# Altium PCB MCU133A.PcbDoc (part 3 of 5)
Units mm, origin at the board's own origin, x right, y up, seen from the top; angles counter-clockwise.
Board outline 58.42 x 139.7 mm, 4 copper layers (Top Signal, GND, PWR, Bottom Signal), stack 1.565 mm thick; 278 components, 226 nets, 1057 pads, 868 vias.
Unrouted connection lines stored in the file: 237.
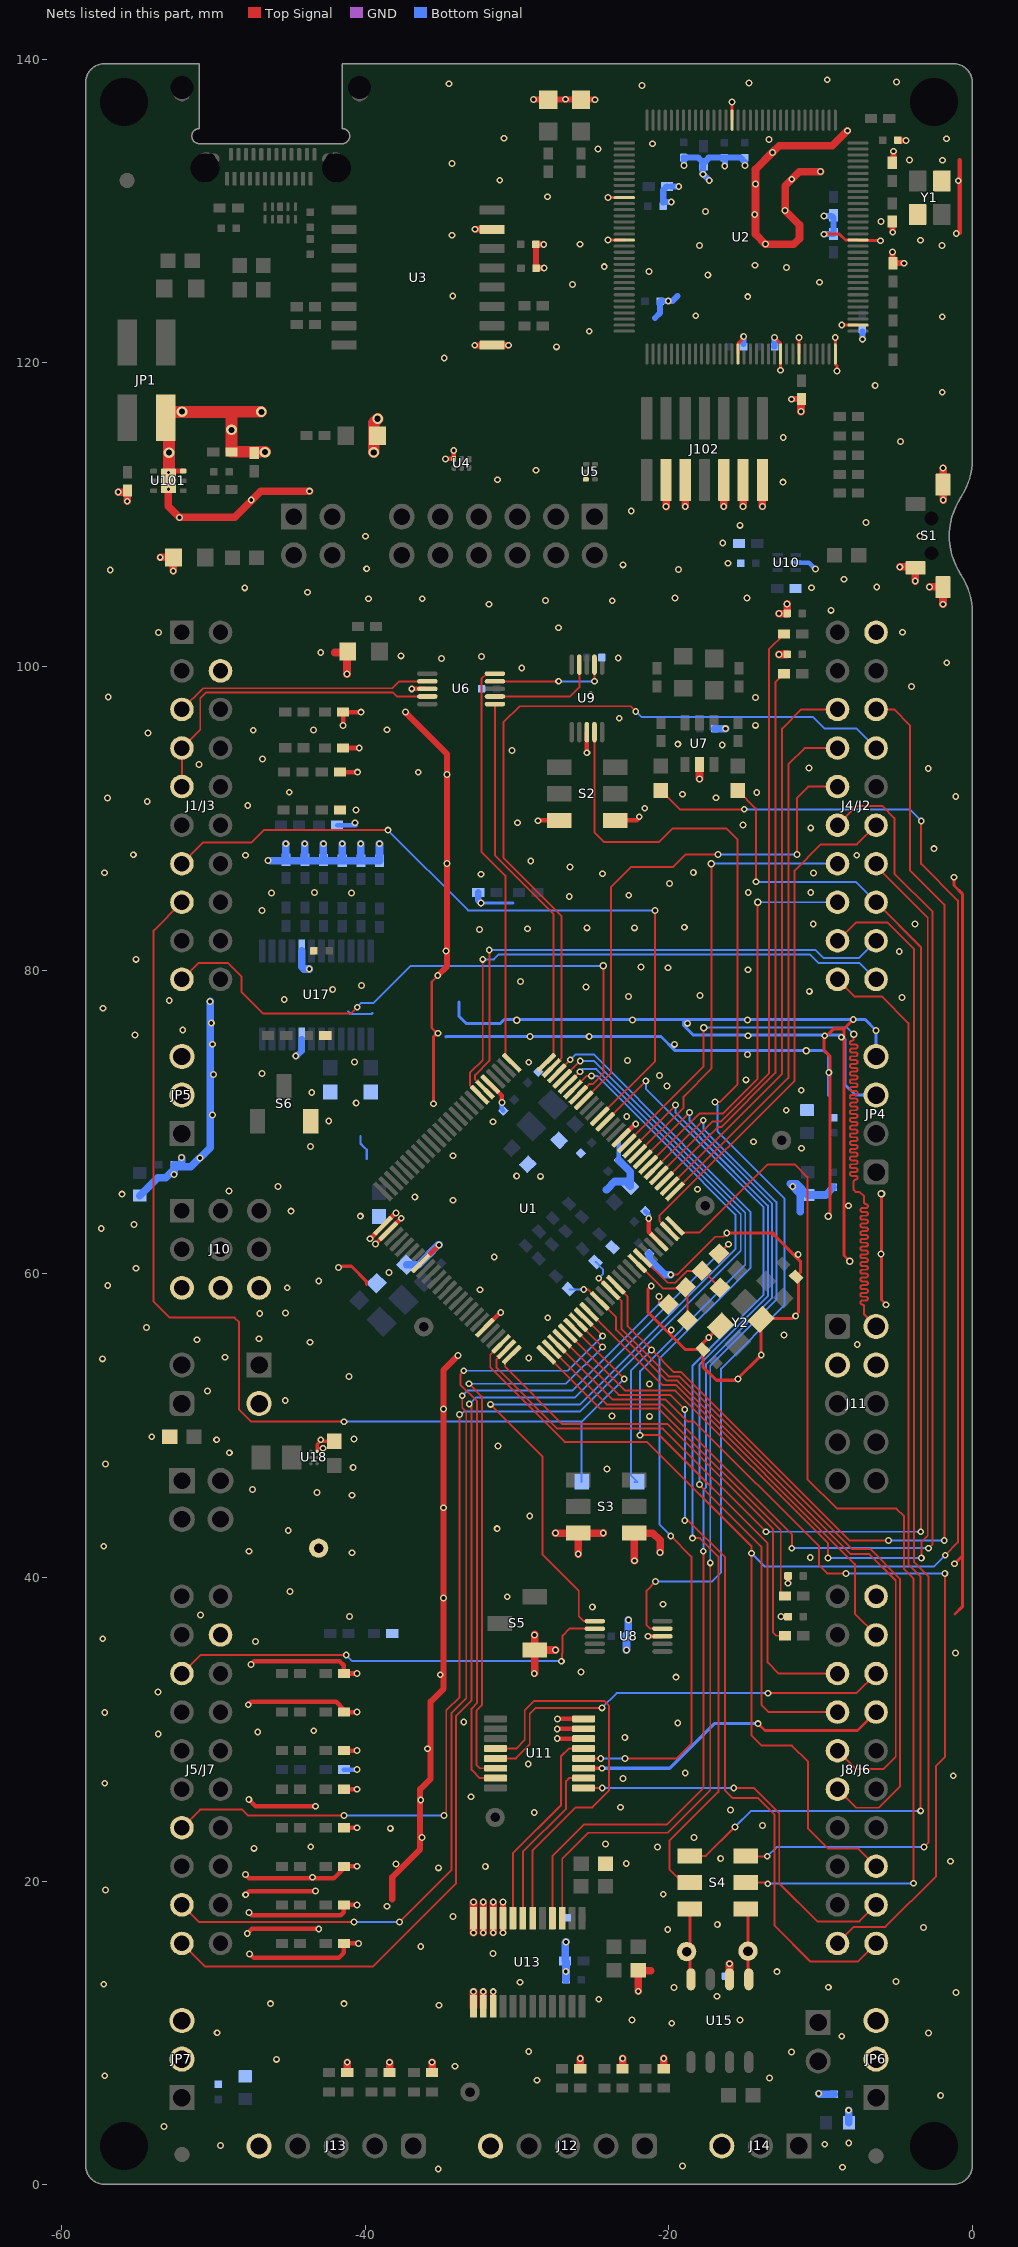
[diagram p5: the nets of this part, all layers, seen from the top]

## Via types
v1: diameter 0.45, hole 0.25, Top Signal to Bottom Signal, tented both sides, 822 vias
v2: diameter 0.5, hole 0.3, Top Signal to Bottom Signal, tented both sides, 22 vias
v3: diameter 0.7, hole 0.4, Top Signal to Bottom Signal, tented both sides, 17 vias
v4: diameter 0.4, hole 0.2, Top Signal to Bottom Signal, tented both sides, 5 vias
v5: diameter 0.5, hole 0.2, Top Signal to Bottom Signal, tented both sides, 2 vias

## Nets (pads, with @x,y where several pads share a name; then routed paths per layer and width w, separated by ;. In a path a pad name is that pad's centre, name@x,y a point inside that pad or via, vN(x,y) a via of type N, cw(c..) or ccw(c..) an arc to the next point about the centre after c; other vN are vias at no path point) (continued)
GND: C1.1 C2.1 C6.2 C7.2 C9.1 C10.1 C11.1 C12.1 C14.1 C15.2 C16.2 C17.2 C18.1 C19.1 C20.1 C21.1 C22.1 C24.2 C25.2 C26.2 C27.2 C28.2 C29.2 C30.2 C31.2 C32.2 C33.2 C34.2 C35.2 C36.2 C37.2 C38.2 C39.2 C40.2 C41.2 C42.2 C43.2 C44.1 C45.2 C46.1 C50.1 C51.1 C52.1 C53.1 C54.1 C55.1 C56.2 C57.2 C58.1 C59.2 C60.1 C61.2 C62.2 C63.2 C64.2 C65.1 C66.1 C67.2 C68.2 C69.2 C70.2 C71.2 C72.2 C73.2 C74.2 C75.2 C76.2 C77.2 C78.2 C81.1 C82.1 C83.1 C84.1 C100.2 C103.2 C107.2 C108.2 C109.2 C110.2 C111.1 C112.1 C113.1 C114.2 C115.1 C116.2 C117.1 C118.2 C119.1 C120.2 C121.2 C122.2 J1/J3.22 J4/J2.20 J5/J7.62 J8/J6.60 J10.7 J10.8 J10.9 J11.3 J11.4 J12.5 J13.5 J14.3 J15.2 J102.3 J102.5 J102.9 J102.11 J102.13 JP1.4 JP4.3 JP4.4 JP5.2 JP5.3 JP6.2 JP6.3 JP7.2 JP7.3 LED0.1 LED1.1 LED2.2 LED3.2 LED6.1 R52.1 R53.2 R67.1 R68.1 R83.2 R102.1 R107.2 R108.2 S1.1 S1.2 S1.3 S2.3 S2.6 S3.1 S3.4 S5.1 S6.3 TP6.1 U1.5 U1.26 U1.27 U1.33 U1.45 U1.72 U1.86 U2.10 U2.17 U2.48 U2.55 U2.58 U2.64 U2.66 U2.80 U2.114 U3.9 U3.15 U4.3 U5.3 U6.3 U7.2 U8.3 U9.3 U10.5 U11.6 U11.7 U11.8 U13.9 U13.10 U13.11 U13.12 U13.13 U13.14 U13.15 U15.2 U17.5 U17.20 U18.A2 U101.3 U101.7@-52.96,112.224 Y1.2 Y1.4 Y2.2 Y2.4 | length 575.8
  Top Signal w0.127: v1(-19.871,59.94) -19.436,59.94 -16.937,62.438 -16.43,62.438 v1(-16.189,62.68)
  Top Signal w0.15: v1@-35.273,75.837 -35.621,76.184 -35.621,79.234 v1(-35.218,79.637)
  Top Signal w0.2: -41.506,60.494 -40.909,60.494 -39.921,59.506 -39.921,59.302 ; v1(-35.496,71.197) -35.496,75.614 v1@-35.273,75.837 ; v1(-24.012,128.084) U2.17@-22.936,128.084 ; v1(-24.012,130.884) U2.10@-22.936,130.884 ; v1(-21.159,59.19) -21.388,58.961 -21.388,57.479 -18.929,55.02 C41.2@-17.757,55.02 ; Y2.4@-16.605,56.566 -17.757,55.414 C41.2@-17.757,55.02 ; v1(-16.189,62.68) -13.188,62.68 ; U2.114@-15.836,135.984 v1(-15.836,137.174) ; U2.48@-15.436,120.584 -15.436,121.294 -15.072,121.658 v1(-15.072,121.739) ; -13.075,62.567 -11.34,60.832 -11.34,60.076 C42.2@-11.616,59.8 -11.456,59.64 -11.456,57.456 -11.86,57.053 -13.855,57.053 Y2.2@-13.918,56.991 v1(-13.918,54.64) -15.571,52.986 -16.867,52.986 -17.757,53.876 C41.2@-17.757,55.02 ; v1(-13.034,121.675) -13.032,121.675 -12.636,121.279 v1(-12.636,119.508) ; U2.58@-11.436,120.584 v1(-11.436,121.66) ; v1(-9.78,128.474) -8.752,128.474 -8.362,128.084 U2.80@-7.536,128.084 -7.506,128.054 -6.07,128.054 v1(-6.061,128.046) ; v2@-9.399,63.888 -9.399,74.334 -9.78,74.715 -9.78,75.503 -9.145,76.138 -8.459,76.138 ; v1(-9.036,121.66) U2.64@-9.036,120.584 -9.036,119.91 -8.917,119.791 v1(-8.917,119.453) ; v1(-8.612,122.484) U2.66@-7.536,122.484 ; v2(-8.078,60.825) -8.459,61.206 -8.459,76.138 ; v1(-7.85,76.747) -8.459,76.138 ; v2(-5.995,65.259) -5.995,58.266 v1(-5.691,57.961) ; v1(-1.22,86.12) -1.22,85.568 -0.646,84.994 -0.646,41.442 ; v1(-1.183,40.904) -0.646,41.442 ; -1.153,37.584 -0.646,38.092 -0.646,41.442 ; -0.646,42.747 -0.646,41.442
  Top Signal w0.23: U18.A2@-43.171,48.298 -43.171,48.772 -42.978,48.965 C110.2@-42.037,48.965
  Top Signal w0.3: U101.7@-52.96,112.224 -52.96,112.491 -52.921,112.53 -52.577,112.874 U101.3@-51.985,112.874 ; v1(-47.883,20.422) -47.653,20.192 -42.058,20.192 -41.403,20.847 C75.2@-41.403,20.969 v1(-40.539,20.969) ; v1(-47.873,19.097) -47.631,19.339 v1(-43.281,19.339) ; v1(-47.771,16.552) -47.479,16.844 v1(-43.063,16.844) ; v1(-47.698,31.614) -47.511,31.802 -41.908,31.802 -41.403,31.296 C37.2@-41.403,31.129 v1(-40.539,31.129) ; v1(-47.664,25.374) -47.222,24.932 v1(-43.271,24.932) ; v1(-47.658,17.937) -47.466,17.744 -41.606,17.744 -41.403,17.947 C38.2@-41.403,18.429 v1(-40.539,18.429) ; v1(-47.616,15.202) -47.353,14.939 -41.728,14.939 -41.403,15.265 C25.2@-41.403,15.889 -40.44,15.889 v1(-40.438,15.887) ; v1(-47.523,34.272) -47.306,34.489 -41.688,34.489 -41.403,34.204 C107.2@-41.403,33.669 v1(-40.539,33.669) ; C31.2@-41.661,93.039 v1(-40.514,93.039) ; C39.2@-41.456,94.629 -40.398,94.629 v1(-40.39,94.637) ; v1@-41.454,96.111 C28.2@-41.454,96.999 -40.293,96.999 v1(-40.285,96.991) ; C40.2@-41.403,23.509 v1(-40.539,23.509) ; C27.2@-41.403,26.049 v1(-40.539,26.049) ; C35.2@-41.403,28.589 v1(-40.539,28.589) ; v1(-39.677,62.309) U1.26@-38.828,63.159 v1(-37.979,64.008) ; v1(-39.324,61.956) U1.27@-38.475,62.805 v1(-37.625,63.654) ; v1(-36.933,98.527) U6.3@-36.072,98.527 ; U1.33@-36.353,60.684 -35.133,61.903 v1(-35.129,61.903) ; v1(-34.704,113.668) -34.165,113.668 U4.3@-34.154,113.679 ; U4.3@-34.165,113.69 v1(-34.165,114.229) ; U1.45@-32.111,56.441 v1@-31.105,57.447 ; U1.5@-31.757,72.492 -31.006,71.741 -31.006,71.285 v1(-30.994,71.273) ; v1@-28.67,89.865 S2.3@-27.224,89.865 ; v1(-27.353,30.022) -27.346,30.029 U11.7@-25.613,30.029 ; v1(-27.348,29.392) -27.336,29.379 U11.6@-25.613,29.379 ; v1(-27.326,30.673) -27.32,30.679 U11.8@-25.613,30.679 ; v1(-25.401,94.315) -25.398,94.317 U9.3@-25.398,95.674 ; S2.6@-23.524,89.865 -22.116,89.865 v1@-21.911,90.07 ; U1.86@-23.13,68.957 -22.223,69.864 v1(-22.175,69.864) v1@-22.175,69.882 ; v1(-21.363,36.121) U8.3@-20.42,36.121 ; v1(-21.321,63.644) -21.321,62.763 U1.72@-20.655,62.098 ; -13.188,62.68 -13.075,62.567 ; v1(-12.611,37.419) C81.1@-12.149,37.419 ; C82.1@-12.148,40.094 -12.148,39.614 v1(-12.146,39.612) ; -0.839,128.561 -0.839,133.339
  Top Signal w0.4: -38.218,18.802 -38.218,20.262 -36.383,22.097 -36.383,26.052 -35.696,26.739 -35.696,31.809 -34.836,32.669 -34.836,53.669 v1(-33.893,54.612) ; v1(-37.351,97.004) -37.351,96.974 -34.606,94.229 -34.606,80.267 v1@-35.227,79.645 ; v1(-32.781,121.154) U3.9@-32.277,121.154 ; v1(-32.761,128.798) U3.15@-31.609,128.798 ; U13.15@-31.569,11.701 v1(-31.569,12.714) ; U3.9@-31.057,121.158 v1(-30.553,121.158) ; v1(-30.919,16.589) U13.9@-30.919,17.602 ; U13.9@-30.919,17.601 v1(-30.919,18.614) ; v1(-28.909,137.336) LED3.2@-28.405,137.336 ; C1.1@-28.755,127.66 -28.755,126.255 C2.1@-28.736,126.236 ; C1.1@-28.755,127.787 v1(-28.238,127.787) ; C2.1@-28.716,126.254 v1(-28.212,126.254) ; LED3.2@-27.692,137.358 LED2.2@-26.301,137.358 ; LED2.2@-25.36,137.331 v1(-24.856,137.331) ; v1(-11.925,117.604) R68.1@-11.421,117.604 ; R67.1@-5.267,126.794 v1(-5.267,127.298) ; v1(-5.257,128.604) C62.2@-5.257,129.108 ; C63.2@-5.207,133.429 v1(-5.207,133.933) ; R67.1@-5.013,126.563 v1(-4.509,126.563) ; C50.1@-4.889,134.64 v1(-4.385,134.64)
  Top Signal w0.5: v1(-56.271,111.484) -55.675,111.484 v1(-55.675,110.888) ; v1(-53.504,107.188) LED6.1@-52.643,107.188 ; U101.7@-52.96,112.224 -52.96,110.544 v1(-52.233,109.817) -48.605,109.817 -46.874,111.548 -46.873,111.547 v1(-43.669,111.547) ; v1(-52.643,106.293) LED6.1@-52.643,107.154 ; -42.007,100.922 LED1.1@-41.214,100.922 ; v1@-41.198,99.499 -41.198,100.906 LED1.1@-41.214,100.922 ; C73.2@-41.184,7.38 v1(-41.184,8.059) ; LED1.1@-41.157,100.979 LED1.1@-41.214,100.922 ; C72.2@-38.39,7.38 v1(-38.39,8.059) ; C71.2@-35.596,7.38 v1(-35.596,8.059) ; U13.13@-32.869,11.701 v1(-32.869,12.714) ; v1(-32.869,16.589) U13.12@-32.869,17.602 ; U13.12@-32.869,17.601 v1(-32.869,18.614) ; U13.14@-32.219,11.701 v1(-32.219,12.714) ; U13.11@-32.219,17.601 v1(-32.219,18.614) ; U13.11@-32.219,17.602 v1(-32.219,16.589) ; v1(-31.569,16.589) U13.10@-31.569,17.602 ; U13.10@-31.569,17.601 v1(-31.569,18.614) ; v1@-28.84,33.687 S5.1@-28.84,35.222 ; v1@-28.84,36.244 S5.1@-28.84,35.222 ; v1(-27.464,35.218) -28.836,35.218 S5.1@-28.84,35.222 ; v1(-27.464,42.916) S3.4@-25.974,42.916 ; v1(-25.97,41.538) -25.974,41.542 S3.4@-25.974,42.916 ; C70.2@-25.836,7.634 v1(-25.836,8.313) ; v1(-24.325,42.927) -24.336,42.916 S3.4@-25.974,42.916 ; C69.2@-23.042,7.634 v1(-23.042,8.313) ; v1(-22.264,41.092) -22.274,41.102 S3.1@-22.274,42.916 -21.051,42.916 -20.575,42.44 v1(-20.575,41.645) ; v1(-22.017,12.739) R53.2@-22.017,14.111 -21.987,14.141 -21.927,14.081 -21.191,14.081 ; S3.1@-22.015,42.902 -21.062,42.902 ; C68.2@-20.331,7.634 v1(-20.331,8.313) ; J102.3@-20.189,112.279 -20.183,112.273 v1(-20.183,110.535) ; v1(-18.919,110.541) J102.5@-18.919,112.279 ; v1(-17.983,92.594) U7.2@-17.983,93.547 ; v1(-16.379,110.541) J102.9@-16.379,112.279 ; U15.2@-16.006,13.526 v1(-16.006,14.557) ; v1(-15.109,110.541) J102.11@-15.109,112.279 ; v1(-13.839,110.541) J102.13@-13.839,112.279 ; v1(-12.752,100.786) C83.1@-12.21,100.786 ; v1(-12.752,103.48) C84.1@-12.21,103.48 ; C84.1@-12.21,103.492 v1(-12.21,104.117) ; v1(-11.294,116.786) R68.1@-11.294,117.647 ; v1(-10.011,132.594) -11.395,132.594 v1(-11.901,132.088) -12.341,131.648 v1(-12.341,130.032) -11.395,129.086 -11.395,128.18 -11.776,127.799 -13.616,127.799 v1(-13.641,127.824) -14.291,128.474 v1(-14.291,131.774) -14.291,132.74 v1(-13.177,133.854) -12.737,134.294 -9.226,134.294 v1(-8.236,135.284) ; v1(-4.785,106.56) S1.3@-3.924,106.56 ; v1(-3.766,105.621) S1.3@-3.766,106.482 ; v1(-2.827,105.241) S1.1@-1.966,105.241 ; v1(-1.944,104.098) S1.1@-1.944,104.959 ; S1.2@-1.936,112.207 v1(-1.936,113.068) ; v1(-1.926,110.964) S1.2@-1.926,111.825
  Top Signal w0.762: U101.7@-52.921,112.53 v3(-52.921,114.082) -52.921,116.17 JP1.4@-53.137,116.386 -52.764,116.759 -49.023,116.759 ; v3(-46.839,116.766) -49.016,116.766 -49.023,116.759 ; v3@-46.572,114.136 R102.1@-48.804,114.136 -48.804,116.54 -49.023,116.759 ; v3(-39.439,114.103) -39.439,116.045 -39.175,116.308 v3(-39.185,116.318)
  Bottom Signal w0.15: -41.123,77.269 -40.963,77.109 -39.588,77.109 -39.521,77.177 ; -40.315,69.067 -40.315,68.572 -40.075,68.333 ; -40.075,68.331 -39.904,68.161 -39.904,67.555
  Bottom Signal w0.2: -34.688,75.604 -34.663,75.63 v1(-25.249,75.63) -20.52,75.63 -19.581,74.69 v2(-10.948,74.69) -9.755,74.69 -9.475,74.411 -9.475,71.744 ; -33.81,77.89 -33.81,76.938 -33.366,76.493 -31.091,76.493 -30.837,76.747 -19.031,76.747 ; v1(-32.372,84.418) -30.266,84.418 ; JP4.3@-6.351,71.769 -7.71,71.769 -8.391,72.45 -8.391,75.467 -8.638,75.714 -18.379,75.714 -19.031,76.366 -19.031,76.747 ; JP4.4@-6.351,74.309 v1(-6.351,76.028) -7.07,76.747 v1(-7.85,76.747) -19.031,76.747
  Bottom Signal w0.3: C36.2@-41.854,89.549 v1@-40.614,89.549 ; C29.2@-41.403,27.344 v1(-40.539,27.344) ; v1(-30.994,71.273) -30.994,70.833 C10.1@-30.902,70.742 ; C11.1@-23.3,67.474 -23.3,68.791 -22.227,69.864 v1(-22.175,69.864) ; C12.1@-21.557,64.128 -21.321,63.892 v1(-21.321,63.644) ; U10.5@-11.636,106.846 -10.786,106.846 -10.354,106.415 v1(-10.339,106.415)
  Bottom Signal w0.4: v1(-44.576,74.345) -44.507,74.345 -44.181,74.672 U17.20@-44.181,75.463 ; -20.911,122.954 -20.572,123.293 C55.1@-20.572,124.045 ; C55.1@-20.547,124.07 v1(-20.043,124.07) -19.765,124.07 -19.441,124.394 ; -20.37,130.572 -20.37,131.38 C57.2@-20.128,131.622 ; -20.345,130.597 v1(-19.841,130.597) ; C57.2@-19.848,131.605 v1(-19.344,131.605) ; C52.1@-19.031,133.522 -18.165,133.522 -18.16,133.517 -18.049,133.517 -17.815,133.283 -17.815,133.167 C61.2@-17.715,133.067 ; v1(-19.006,132.993) C52.1@-19.006,133.497 ; C61.2@-17.676,133.144 -17.676,133.206 C61.2@-17.615,133.267 ; v1(-17.333,132.015) -17.765,132.446 -17.765,133.255 -17.627,133.255 C61.2@-17.615,133.267 ; -17.333,133.517 -17.333,133.501 -17.567,133.267 C61.2@-17.615,133.267 ; v1(-16.312,132.968) C60.1@-16.312,133.472 ; -15.292,133.522 -17.265,133.522 -17.27,133.517 -17.38,133.517 -17.615,133.283 C61.2@-17.615,133.267 ; -15.267,133.497 -14.987,133.217 v1(-14.987,132.993) ; C54.1@-15.072,121.235 v1(-15.072,121.739) ; C53.1@-13.057,121.077 -13.034,121.1 v1(-13.034,121.675) ; v1(-9.78,128.474) C56.2@-9.276,128.474 ; v1(-9.78,129.675) -9.276,129.675 -9.165,129.564 C56.2@-9.165,128.481 ; v1(-7.252,121.551) C66.1@-7.252,122.055
  Bottom Signal w0.45: C17.2@-32.554,85.114 -32.554,84.601 v1(-32.372,84.418)
  Bottom Signal w0.5: C115.1@-54.853,65.142 -53.664,66.332 -53.144,66.332 -52.587,66.888 C116.2@-52.587,67.172 ; v1@-52.587,66.649 C116.2@-52.587,67.172 ; v1(-52.096,67.654) -52.096,67.172 C116.2@-52.587,67.172 ; v1(-50.217,77.941) -50.217,68.311 -51.491,67.037 -52.452,67.037 C116.2@-52.587,67.172 ; v1@-46.262,87.205 C76.2@-41.512,87.205 ; v1@-45.226,88.305 -45.226,87.282 C26.2@-45.211,87.266 ; U17.5@-44.181,81.263 -44.181,80.222 -44.032,80.074 v1(-43.686,80.074) ; C34.2@-43.976,87.268 v1@-43.976,88.306 ; C32.2@-42.755,87.264 v1(-42.755,88.318) ; v1(-41.512,88.318) C76.2@-41.512,87.205 ; v1(-40.289,88.318) C78.2@-40.289,87.205 ; v1(-39.057,88.318) C77.2@-39.057,87.205 C78.2@-40.289,87.205 ; C15.2@-37.274,60.592 -36.485,60.592 -35.173,61.903 v1(-35.129,61.903) ; C65.1@-26.771,13.489 -26.771,14.667 C67.2@-26.829,14.725 -26.829,15.933 v1(-26.771,15.991) ; -24.106,65.542 -23.568,66.079 -22.834,66.079 C9.1@-22.529,65.775 -22.529,66.703 C11.1@-23.3,67.474 ; v1(-22.792,35.218) -22.786,35.224 C45.2@-22.786,36.121 -22.661,36.246 v1(-22.661,37.193) ; C21.1@-21.288,61.316 -21.288,60.949 -20.279,59.94 v1(-19.871,59.94) ; C44.1@-16.976,95.911 -16.969,95.904 v1(-16.262,95.904) ; -11.336,64.087 -11.336,65.238 -12.015,65.917 -11.591,65.917 C111.1@-10.859,65.186 -9.674,65.186 C112.1@-9.17,65.689 ; v1(-10.121,5.999) -10.08,5.958 C118.2@-9.111,5.958 ; v1(-8.156,4.899) -8.141,4.884 C117.1@-8.141,4.078 ; C76.2@-41.512,87.205 C78.2@-40.289,87.205
  other v1: -35.183,1.036 -8.561,1.144 -19.096,1.224 -49.531,2.586 -9.726,2.664 -8.151,2.747 -53.244,3.835 -2.096,5.881 -28.682,6.875 -13.371,7.037 -57.151,7.177 -34.09,7.8 -45.837,8.256 -11.923,8.747 -29.222,8.78 -8.611,9.772 -49.751,10.008 -2.888,9.992 -19.803,10.628 -22.422,10.854 -15.321,10.854 -35.135,11.814 -46.247,11.924 -41.403,11.924 -24.613,12.214 -16.832,12.416 -1.076,12.665 -19.652,12.995 -9.494,13.002 -57.22,13.197 -29.805,13.339 -5.034,13.38 -12.875,14.031 -26.784,14.05 -31.573,15.229 -36.343,15.687 -20.067,16.802 -3.231,16.932 -16.805,17.134 -34.225,17.662 -38.561,18.337 -20.365,19.132 -57.096,19.417 -43.463,20.249 -35.168,20.869 -32.086,20.954 -37.966,21.127 -22.8,21.147 -1.443,21.307 -16.587,21.49 -47.323,22.154 -20.753,22.235 -43.583,22.262 -24.163,22.444 -36.261,22.867 -18.34,22.875 -38.343,23.472 -13.825,23.661 -28.861,24.519 -15.938,24.677 -23.179,24.855 -36.341,25.337 -33.023,25.554 -57.158,26.445 -23.017,26.76 -1.271,26.932 -18.918,27.117 -29.261,27.717 -35.904,28.717 -22.898,29.459 -53.628,29.688 -47.076,29.809 -43.386,29.904 -19.413,30.402 -33.511,30.469 -57.158,31.109 -53.656,32.46 -19.533,33.429 -35.055,33.584 -28.861,33.669 -25.781,33.762 -1.113,35.024 -47.22,35.771 -57.282,35.961 -28.84,36.209 -41.039,37.428 -50.852,37.53 -25.039,38.051 -20.377,38.235 -34.836,38.639 -30.641,38.725 -44.959,39.067 -10.688,41.317 -40.863,41.619 -47.651,41.721 -57.22,42.056 -45.065,43.093 -31.308,43.211 -29.16,44.044 -34.836,44.589 -40.878,45.411 -43.168,45.584 -47.423,45.789 -24.064,47.144 -40.793,47.233 -57.096,47.467 -48.948,48.207 -42.775,48.503 -31.253,48.651 -49.783,49.067 -42.927,49.061 -40.743,49.112 -54.061,49.269 -21.276,50.608 -23.751,50.626 -34.836,51.099 -45.264,51.652 -50.391,52.272 -21.267,52.747 -15.443,53.075 -41.073,53.227 -57.303,54.395 -29.222,54.446 -49.226,54.497 -7.593,55.335 -43.638,55.488 -51.083,55.656 -46.991,55.716 -17.375,55.796 -12.413,55.968 -19.838,56.292 -54.408,56.453 -27.978,57.1 -11.647,57.215 -46.94,57.38 -45.251,57.415 -31.075,57.447 -32.437,58.948 -45.137,59.075 -56.96,59.224 -43.056,59.532 -38.431,60.085 -55.094,60.364 -41.759,60.422 -31.495,61.097 -11.482,61.264 -6.016,61.304 -57.382,62.989 -55.221,63.242 -40.32,63.793 -44.883,64.124 -8.167,64.479 -34.215,64.844 -36.729,65.063 -56.021,65.243 -48.971,65.454 -18.116,65.568 -45.736,65.747 -11.841,65.74 -28.449,66.417 -30.024,66.447 -52.587,66.547 -50.888,67.627 -34.215,67.769 -11.253,68.264 -43.596,68.391 -14.415,68.699 -31.573,70.016 -42.406,70.067 -22.772,70.368 -50.053,70.459 -12.269,70.77 -40.596,71.253 -43.518,71.944 -11.279,72.087 -20.114,72.358 -14.911,72.772 -20.607,73.056 -50.001,73.122 -46.803,73.199 -9.461,73.257 -29.227,73.928 -40.704,73.953 -22.718,74.053 -14.809,74.436 -50.066,75.119 -19.635,75.111 -8.638,75.579 -29.153,75.637 -14.794,75.681 -9.731,75.681 -55.17,75.731 -35.211,75.837 -52.02,76.062 -18.774,76.493 -50.133,76.512 -22.4,76.714 -14.819,76.722 -57.278,77.484 -52.909,77.992 -45.333,78.072 -4.637,78.195 -22.666,78.27 -17.951,78.322 -10.745,78.602 -42.143,78.724 -25.464,78.881 -40.245,78.984 -29.762,79.241 -14.794,80.024 -20.054,80.156 -21.832,80.206 -55.094,80.71 -4.821,81.218 -34.668,81.259 -32.464,82.666 -29.304,82.728 -25.39,82.785 -22.254,82.785 -18.979,82.818 -10.491,83.047 -3.786,83.047 -46.788,83.936 -26.56,84.85 -22.639,84.926 -46.178,85.079 -40.898,85.079 -43.346,85.104 -14.768,85.114 -10.653,85.114 -19.965,85.714 -32.372,86.313 -24.371,86.346 -57.176,86.411 -10.473,86.399 -18.385,86.437 -26.503,86.794 -34.606,87.027 -29.095,87.187 -46.407,87.212 -47.88,87.568 -7.62,87.568 -55.271,87.593 -2.541,88 -45.226,88.318 -43.976,88.318 -10.653,89.371 -15.114,89.549 -40.673,89.712 -29.973,89.712 -28.625,89.84 -21.945,90.104 -40.614,90.549 -21.591,90.667 -47.733,90.848 -54.357,91.098 -56.973,91.327 -16.892,91.352 -1.106,91.429 -19.102,91.581 -45.006,91.717 -14.212,91.708 -34.606,92.879 -36.501,93.029 -2.917,93.283 -10.762,93.308 -50.938,93.547 -46.771,93.902 -30.331,94.473 -16.486,94.824 -19.407,94.883 -54.306,95.62 -47.371,95.797 -43.41,95.823 -38.558,95.836 -41.454,96.111 -14.291,96.122 -23.27,96.585 -14.291,97.956 -56.922,97.982 -25.147,98.12 -4.014,98.685 -41.202,99.499 -29.685,99.893 -1.698,100.249 -34.977,100.522 -23.336,100.566 -32.338,100.649 -37.644,100.7 -42.927,100.928 -53.608,102.239 -4.605,102.255 -27.271,102.547 -9.323,103.697 -31.853,104.103 -23.725,104.332 -28.132,104.345 -39.777,104.459 -36.247,104.459 -19.595,104.51 -14.86,104.51 -43.803,104.891 -47.933,105.179 -10.606,105.181 -6.306,105.241 -8.459,105.745 -56.795,106.364 -19.356,106.396 -39.904,106.44 -23.015,106.694 -16.103,106.796 -16.454,108.142 -39.981,108.574 -3.454,108.599 -15.314,109.296 -7.008,109.487 -22.479,110.244 -47.506,110.957 -12.49,112.14 -31.288,112.301 -28.757,112.923 -4.749,114.812 -12.467,115.082 -1.994,118.057 -6.41,118.51 -34.793,120.314 -27.401,121.053 -25.241,122.084 -1.994,123.034 -18.231,123.106 -14.799,124.358 -34.237,124.408 -26.341,125.153 -10.071,125.304 -17.431,125.784 -21.301,126.024 -12.241,126.284 -24.251,126.334 -14.334,126.431 -17.971,127.734 -1.999,127.719 -25.852,127.807 -3.417,128.069 -34.286,128.4 -1.074,128.513 -6.021,129.3 -14.341,129.773 -17.581,129.977 -27.992,130.943 -0.941,131.992 -31.136,132.031 -17.753,132.417 -34.286,133.123 -1.982,133.347 -4.141,133.364 -24.666,134.084 -21.068,134.426 -13.408,134.719 -1.719,134.756 -30.849,134.789 -26.805,137.358 -21.763,138.266 -34.481,138.381 -14.728,138.422 -5.007,138.503 -9.561,138.645
  other v2: -9.494,63.793 -30.016,76.697
  other v3: -46.601,114.117 -48.803,115.581 -52.068,116.782
  other v5: -52.96,111.674 -52.96,112.774
GPIO0: R8.1 U1.79 | length 39.4
  Top Signal w0.127: U1.79@-20.655,66.482 -17.096,70.042 -16.559,70.042 -13.411,73.189 -13.411,101.136 R8.1@-12.413,102.134
GPIO1: R9.1 U1.78 | length 36.8
  Top Signal w0.127: U1.78@-20.302,66.128 -16.775,69.655 -16.553,69.655 -12.98,73.228 -12.98,98.957 R9.1@-12.413,99.524
GPIO2: J4/J2.38 U1.77 | length 37.4
  Top Signal w0.127: U1.77@-19.948,65.775 -12.536,73.187 -12.536,95.911 -11.279,97.169 J4/J2.38@-8.891,97.169
GPIO3: J4/J2.37 U1.76 | length 34.9
  Top Signal w0.127: U1.76@-19.595,65.421 -12.121,72.895 -12.121,93.568 -11.06,94.629 J4/J2.37@-8.891,94.629
GPIO4: S4.2 U1.75 | length 73.9
  Top Signal w0.127: U1.75@-19.595,63.159 -19.142,62.706 -17.992,62.706 -13.496,67.202 -11.709,67.202 -10.867,66.36 -10.867,46.48 -8.913,44.527 -5.016,44.527 -4.502,44.012 -4.502,40.542 -3.878,39.919 v1(-3.878,19.851) v1@-3.878,19.844 ; S4.2@-14.932,19.903 -13.565,19.903 v1(-13.488,19.826)
  Bottom Signal w0.127: v1(-13.488,19.826) -13.463,19.851 v1(-3.878,19.851)
GPIO4_BP: J4/J2.32 S4.3 | length 79.7
  Top Signal w0.127: S4.3@-14.932,21.653 -14.908,21.629 v1(-13.514,21.629) ; J4/J2.32@-8.891,81.929 -7.672,83.148 -5.614,83.148 -3.859,81.392 -3.859,77.379 -3.859,41.022 ; -3.859,42.754 -3.859,41.022 ; v1(-3.201,22.239) -2.903,22.537 -2.903,40.067 -3.859,41.022
  Bottom Signal w0.127: v1(-13.514,21.629) -12.904,22.239 v1(-3.201,22.239)
GPIO4_CANTX: S4.1 TP7.1 U15.1 | length 4.7
  Top Signal w0.2: U15.1@-14.794,13.526 -14.794,15.381 -14.794,16.221 S4.1@-14.794,18.015
  Top Signal w0.5: S4.1@-14.932,18.153 S4.1@-14.794,18.015
GPIO5: S4.5 U1.89 | length 64.9
  Top Signal w0.127: U1.89@-24.191,70.018 v1(-21.515,72.694) ; S4.5@-18.632,19.903 -19.081,19.903 -19.965,20.787 -19.965,22.645 -16.733,25.877 -16.733,41.37 -17.948,42.584 v1(-18.441,42.584)
  Bottom Signal w0.127: v1(-21.515,72.694) -21.515,72.174 -18.192,68.851 -18.192,68.813 -13.753,64.375 -13.753,58.633 -18.441,53.945 v1(-18.441,42.584)
GPIO5_BP: J4/J2.31 S4.6 | length 74.5
  Top Signal w0.127: S4.6@-18.632,21.653 -17.554,21.653 v1(-15.647,23.56) ; J4/J2.31@-8.891,79.389 -7.773,78.271 -5.985,78.271 -4.225,76.511 -4.225,40.858 -3.416,40.049 -3.416,24.626 v1(-3.414,24.624)
  Bottom Signal w0.127: v1(-15.647,23.56) -14.581,24.627 -3.417,24.627 v1(-3.414,24.624)
GPIO5_CANRX: S4.4 TP8.1 U15.4 | length 4.6
  Top Signal w0.2: U15.4@-18.604,13.526 -18.604,15.352 S4.4@-18.604,18.125
  Top Signal w0.3: S4.4@-18.632,18.153 S4.4@-18.604,18.125
GPIO6: J8/J6.78 U1.97 | length 58.3
  Top Signal w0.127: U1.97@-27.019,72.846 -25.861,74.004 v1(-25.833,74.004) ; v1(-21.896,49.366) -20.615,49.366 -13.488,42.239 -13.488,34.406 -12.752,33.669 J8/J6.78@-8.891,33.669
  Bottom Signal w0.127: v1(-25.833,74.004) -24.912,74.004 -19.3,68.392 -19.3,68.354 -14.967,64.022 -14.967,60.593 -20.497,54.986 -21.896,53.587 v1(-21.896,49.366)
GPIO7: J8/J6.77 U1.84 | length 54.8
  Top Signal w0.127: U1.84@-22.423,68.25 v1(-19.559,71.114) ; v1(-17.984,46.115) -13.901,42.032 -13.901,31.618 -13.412,31.129 J8/J6.77@-8.891,31.129
  Bottom Signal w0.127: v1(-19.559,71.114) -19.559,70.61 -17.915,68.966 -17.915,68.928 -13.476,64.49 -13.476,58.518 -17.984,54.01 v1(-17.984,46.115)
GPIO8: J4/J2.15 U1.74 | length 34.3
  Top Signal w0.127: U1.74@-19.948,62.805 -20.626,63.482 -20.626,63.811 -11.71,72.726 -11.71,86.552 -9.979,88.283 -7.617,88.283 J4/J2.15@-6.351,89.549
GPIO9: J1/J3.7 U1.90 | length 49.3
  Top Signal w0.127: J1/J3.7@-52.071,87.009 -50.674,88.406 -47.484,88.406 -46.671,89.219 v1(-38.507,89.219) ; U1.90@-24.545,70.371 -20.905,74.01 v1(-20.905,83.936)
  Bottom Signal w0.127: v1(-38.507,89.219) -33.224,83.936 v1(-20.905,83.936)
GPIO10: J4/J2.36 U1.93 | length 34.6
  Top Signal w0.127: U1.93@-25.605,71.432 -23.801,73.236 -23.801,85.485 -22.491,86.794 -19.714,86.794 -18.89,87.619 v1(-16.765,87.619) ; v1(-11.558,87.619) -11.558,91.352 -10.821,92.089 J4/J2.36@-8.891,92.089
  Bottom Signal w0.127: v1(-16.765,87.619) v1(-11.558,87.619)
GPIO11: J4/J2.35 U1.52 | length 84.6
  Top Signal w0.127: U1.52@-27.727,55.027 -24.099,51.399 -20.466,51.399 -11.901,42.834 v1(-11.901,41.924) ; J4/J2.35@-8.891,89.549 -7.64,90.8 -5.926,90.8 -5.144,90.019 -5.144,86.348 -2.633,83.836 -2.633,42.191 v1(-2.9,41.924)
  Bottom Signal w0.127: v1(-11.901,41.924) v1(-2.9,41.924)
GPIO12: R49.1 U1.51 | length 24.7
  Top Signal w0.127: U1.51@-28.08,54.673 -24.529,51.122 -20.654,51.122 -12.628,43.097 -12.628,39.061 R49.1@-12.349,38.781
GPIO13: R50.1 U1.50 | length 30.7
  Top Signal w0.127: U1.50@-30.343,54.673 -30.774,54.242 -30.774,53.861 -27.016,50.103 -20.071,50.103 -13.139,43.17 -13.139,36.367 -12.929,36.157 R50.1@-12.349,36.157
GPIO14: J5/J7.47 U1.96 | length 85.9
  Top Signal w0.127: J5/J7.47@-52.071,23.509 -50.877,24.703 -48.106,24.703 -47.725,24.322 v1(-41.403,24.322) ; v1(-34.801,24.322) -34.661,24.462 -34.661,31.244 -33.784,32.121 v1(-33.784,50.732) ; U1.96@-26.666,72.492 v1(-25.856,73.302)
  Bottom Signal w0.127: v1(-41.403,24.322) v1(-34.801,24.322) ; v1(-33.784,50.732) -33.77,50.718 -33.708,50.718 -33.511,50.916 -25.869,50.916 -15.263,61.521 -15.263,63.926 -19.577,68.24 -19.577,68.277 -24.774,73.475 -25.683,73.475 v1(-25.856,73.302)
GPIO15: U1.95 U8.6 | length 55.1
  Top Signal w0.127: v1(-31.751,51.398) -28.329,47.976 -28.329,41.514 -25.934,39.119 -25.934,37.438 -25.616,37.121 U8.6@-24.87,37.121 ; U1.95@-26.312,72.139 -25.415,73.036 v1(-25.096,73.036)
  Bottom Signal w0.127: v1(-31.751,51.398) -25.846,51.398 -15.622,61.622 -15.622,63.893 -19.854,68.125 -19.854,68.163 -24.728,73.036 v1(-25.096,73.036)
GPIO15_BP: J5/J7.43 U8.7 | length 29.7
  Top Signal w0.127: J5/J7.43@-52.071,33.669 -50.852,34.888 v1(-41.251,34.888) ; v1(-27.08,34.482) -27.025,34.538 -27.025,35.003 -27.001,35.026 -27.001,36.171 -26.552,36.621 U8.7@-24.87,36.621
  Bottom Signal w0.127: v1(-41.251,34.888) -40.844,34.482 v1(-27.08,34.482)
GPIO15_SCIRX: U8.4 U9.4 | length 78.5
  Top Signal w0.127: U9.4@-24.898,95.674 -24.898,89.072 -24.276,88.449 -20.644,88.449 -19.752,89.342 -16.217,89.342 -15.47,88.595 -15.47,72.486 -16.644,71.312 v1(-16.968,71.312) ; v1(-20.871,39.733) -21.469,39.136 -21.469,36.855 -21.234,36.621 U8.4@-20.42,36.621
  Bottom Signal w0.127: v1(-20.871,39.733) -17.152,39.733 -16.557,40.328 -16.557,53.755 -12.368,57.944 -12.368,64.949 -16.807,69.387 -16.807,71.15 v1(-16.968,71.312)
GPIO16: J8/J6.51 U1.54 | length 55.7
  Top Signal w0.127: U1.54@-27.019,55.734 -23.312,52.027 -19.908,52.027 v1(-18.949,51.068) ; v1(-18.949,43.746) -18.718,43.746 -16.291,41.319 -16.291,25.956 -15.8,25.465 -14.123,25.465 -13.038,24.379 -13.038,17.064 -10.669,14.695 -7.545,14.695 J8/J6.51@-6.351,15.889
  Bottom Signal w0.127: v1(-18.949,43.746) v1(-18.949,51.068)
GPIO17: J4/J2.14 U1.55 | length 77.3
  Top Signal w0.127: U1.55@-26.666,56.088 -22.882,52.304 -19.565,52.304 -9.511,42.25 v1(-9.511,41.279) ; J4/J2.14@-6.428,86.932 -2.947,83.45 -2.947,77.662 -2.947,65.311 -2.947,42.747 -3.369,42.325 v1(-3.369,41.279)
  Bottom Signal w0.127: v1(-9.511,41.279) v1(-3.369,41.279)
GPIO18_BP: J5/J7.49 R36.1 | length 68.4
  Top Signal w0.127: J5/J7.49@-52.071,18.429 -50.953,17.311 v1(-40.743,17.311) ; v1(-37.736,17.312) -34.313,20.734 -34.313,31.072 -33.345,32.04 -33.345,50.913 -33.602,51.17 -33.608,51.177 v1(-33.608,51.964) ; v1(-20.651,58.51) -20.651,58.232 -20.4,57.98 R36.1@-20.019,57.98
  Bottom Signal w0.127: v1(-40.743,17.311) v1(-37.736,17.312) ; v1(-33.608,51.964) -33.254,52.318 -26.335,52.318 -20.651,58.002 v1(-20.651,58.51)
GPIO18_X2: R32.1 R36.2 U1.68 | length 6
  Top Signal w0.127: U1.68@-22.07,60.684 -22.033,60.684 -20.391,59.042 -18.92,59.042 -18.774,58.897 R32.1@-18.774,56.92
GPIO19_BP: J5/J7.50 R37.1 | length 75.3
  Top Signal w0.127: J5/J7.50@-52.071,15.889 -50.561,14.379 -39.476,14.379 -34.016,19.839 -34.016,30.877 -32.988,31.904 -32.988,51.257 v1(-33.15,51.418) ; R37.1@-16.693,61.325 v1(-16.079,61.939)
  Bottom Signal w0.127: v1(-33.15,51.418) -33.132,51.418 -32.698,51.852 -26.166,51.852 v1(-16.079,61.939)
GPIO19_X1: R33.1 R37.2 U1.69 | length 6.5
  Top Signal w0.127: U1.69@-21.716,61.037 -20.086,59.407 -19.576,59.407 -18.79,60.193 R37.2@-17.825,60.193 -17.747,60.193 R33.1@-16.632,59.079
GPIO20: J8/J6.53 R34.1 U1.48 | length 133.3
  Top Signal w0.127: U1.48@-31.05,55.38 -31.765,54.666 -31.765,53.831 -26.861,48.928 -21.447,48.928 -14.555,42.036 v1(-14.555,41.594) ; R34.1@-20.523,91.836 -19.278,90.59 v1(-15.038,90.59) ; v1@-14.562,41.67 -14.562,29.612 -13.869,28.919 -11.888,28.919 -10.847,27.878 -10.847,23.486 -9.498,22.137 -7.519,22.137 J8/J6.53@-6.351,20.969 ; v1(-3.379,89.828) -3.379,86.996 -0.959,84.576 -0.959,42.301 ; v1(-1.798,41.462) -0.959,42.301 ; -0.959,43.624 -0.959,42.301
  Bottom Signal w0.127: v1(-15.038,90.59) -4.141,90.59 v1(-3.379,89.828) ; v1(-14.555,41.594) -13.666,40.705 -2.555,40.705 v1(-1.798,41.462)
GPIO21: J4/J2.13 R35.1 U1.49 | length 91.6
  Top Signal w0.127: U1.49@-30.696,55.027 -31.345,54.379 -31.345,53.803 -27.347,49.805 -20.393,49.805 v1(-13.595,43.007) ; R35.1@-15.469,91.836 -14.265,90.632 v1(-14.265,85.815) ; J4/J2.13@-6.351,84.469 -3.405,81.523 v1(-3.405,43.007)
  Bottom Signal w0.127: v1(-14.265,85.815) -7.697,85.815 J4/J2.13@-6.351,84.469 ; v1(-13.595,43.007) v1(-3.405,43.007)
GPIO22: J4/J2.34 U1.83 | length 29.4
  Top Signal w0.127: U1.83@-22.07,67.896 -19.026,70.94 -19.026,71.673 -17.197,73.502 v2(-17.197,87.009)
  Bottom Signal w0.127: v2(-17.197,87.009) J4/J2.34@-8.891,87.009
GPIO23: J4/J2.33 U1.81 | length 26.4
  Top Signal w0.127: U1.81@-21.363,67.189 -17.999,70.553 -16.439,70.553 -14.149,72.843 v2(-14.149,84.469)
  Bottom Signal w0.127: v2(-14.149,84.469) J4/J2.33@-8.891,84.469
GPIO24: J1/J3.8 R38.1 U1.56 | length 74.6
  Top Signal w0.127: J1/J3.8@-52.071,84.469 -53.935,82.605 -53.935,58.171 -52.871,57.107 -48.617,57.107 -48.305,56.795 -48.305,51.046 -47.515,50.255 v1(-41.403,50.255) ; U1.56@-26.312,56.441 -22.946,53.075 v1(-22.937,53.075)
  Bottom Signal w0.127: v1@-41.403,50.268 -25.744,50.268 ; R38.1@-25.744,46.297 -25.744,50.268 ; v1(-22.937,53.075) -25.744,50.268
GPIO25: U1.57 U11.14 | length 39.1
  Top Signal w0.127: v1(-33.154,52.757) -32.308,51.911 -32.308,31.578 -32.682,31.205 -32.682,27.662 -32.449,27.429 U11.14@-31.413,27.429 ; U1.57@-25.934,56.786 -25.979,56.786 v1(-24.363,55.17)
  Bottom Signal w0.127: v1(-33.154,52.757) -26.777,52.757 v1(-24.363,55.17)
GPIO25_BP: J8/J6.58 U11.13 | length 28.6
  Top Signal w0.127: U11.13@-31.413,28.079 -30.077,28.079 -29.16,28.995 -29.16,31.029 -28.781,31.408 v1(-24.41,31.408) ; v1(-13.463,32.374) -7.646,32.374 J8/J6.58@-6.351,33.669
  Bottom Signal w0.127: v1(-24.41,31.408) -23.445,32.374 v1(-13.463,32.374)
GPIO25_Q3A: U11.12 U13.6 | length 26.7
  Top Signal w0.127: U11.12@-31.413,28.729 -30.062,28.729 -29.49,29.3 -29.49,31.256 -28.899,31.847 -24.229,31.847 -23.946,31.565 -23.946,25.947 -25.039,24.855 -26.131,24.855 -28.969,22.018 U13.6@-28.969,17.602
GPIO26: U1.58 U11.15 | length 40.7
  Top Signal w0.127: v1(-33.513,53.609) -33.728,53.394 -33.728,52.704 -32.624,51.6 -32.624,31.729 -32.996,31.358 -32.996,27.319 -32.456,26.779 U11.15@-31.413,26.779 ; U1.58@-25.605,57.148 v1(-24.36,55.903)
  Bottom Signal w0.127: v1(-33.513,53.609) -26.653,53.609 v1(-24.36,55.903)
GPIO26_BP: J8/J6.52 U11.1 | length 26.1
  Top Signal w0.127: U11.1@-25.613,26.129 v1(-24.385,26.129) ; v1(-15.724,26.125) -14.388,26.125 -12.728,24.466 -12.728,19.838 -10.226,17.337 -7.443,17.337 J8/J6.52@-6.351,18.429
  Bottom Signal w0.127: v1(-24.385,26.129) -15.727,26.129 v1(-15.724,26.125)
GPIO26_Q3B: U11.2 U13.7 | length 11.4
  Top Signal w0.127: U13.7@-29.619,17.602 -29.619,21.914 -26.773,24.76 -26.773,26.582 -26.576,26.779 U11.2@-25.613,26.779
GPIO27: J8/J6.59 U1.59 | length 29.6
  Top Signal w0.127: U1.59@-25.252,57.502 -20.434,52.684 -19.554,52.684 -7.748,40.878 -7.748,37.606 J8/J6.59@-6.351,36.209
GPIO28: U1.1 U6.10 | length 27.8
  Top Signal w0.127: U6.10@-31.454,99.523 -32,99.523 -32.342,99.18 -32.342,87.799 -30.767,86.224 -30.767,74.331 U1.1@-30.343,73.907 ; U1.1@-30.343,73.899 U1.1@-29.864,73.42
GPIO28_BP: J1/J3.3 U6.2 | length 16.9
  Top Signal w0.127: J1/J3.3@-52.071,97.169 -50.676,98.564 -38.223,98.564 -37.763,99.023 U6.2@-35.904,99.023
GPIO28_SCIRX: U6.9 U9.7 | length 7.7
  Top Signal w0.127: U6.9@-31.454,99.023 v1(-27.257,99.023) ; v1(-24.898,99.023) U9.7@-24.898,100.124
  Bottom Signal w0.127: v1(-27.257,99.023) v1(-24.898,99.023)
GPIO29: U1.100 U6.6 | length 25.4
  Top Signal w0.127: U6.6@-31.454,97.523 -31.454,87.555 -27.6,83.7 -27.6,74.387 U1.100@-28.08,73.907
GPIO29_BP: J1/J3.4 J1/J3.5 U6.4 | length 22
  Top Signal w0.127: J1/J3.5@-52.071,92.089 -52.071,94.473 J1/J3.4@-51.97,94.574 ; J1/J3.4@-52.071,94.629 -50.864,95.836 -50.864,97.893 -50.471,98.287 -38.173,98.287 -37.909,98.023 U6.4@-35.904,98.023
  Bottom Signal w0.127: J1/J3.4@-52.071,94.629 J1/J3.4@-52.071,95.073
GPIO29_SCITX: U6.7 U9.9 | length 7.3
  Top Signal w0.127: U6.7@-31.454,98.023 -26.503,98.023 -25.898,98.628 U9.9@-25.898,100.124
GPIO30: U1.98 U11.4 | length 63.5
  Top Signal w0.127: U1.98@-27.373,73.199 -26.489,74.084 v1(-26.489,74.093) ; U11.4@-25.613,28.079 -24.489,28.079 v1(-24.487,28.081) ; v1(-22.886,28.081) -19.483,28.081 -18.511,29.053 -18.511,41.373 v1(-19.871,42.733)
  Bottom Signal w0.127: v1(-26.489,74.093) -26.139,74.443 -24.959,74.443 -19.023,68.507 -19.023,68.469 -14.611,64.057 -14.611,60.408 -20.626,54.393 -20.626,43.488 v1(-19.871,42.733) ; v1(-24.487,28.081) v1(-22.886,28.081)
GPIO30_BP: J8/J6.57 U11.3 | length 21.2
  Top Signal w0.2: U11.3@-25.613,27.429 v1(-24.398,27.429) ; v1(-14.123,30.367) -13.666,29.91 -7.57,29.91 J8/J6.57@-6.351,31.129
  Bottom Signal w0.2: v1(-24.398,27.429) -19.944,27.429 -17.006,30.367 v1(-14.123,30.367)
GPIO30_Q3I: U11.5 U13.8 | length 13.6
  Top Signal w0.127: U13.8@-30.269,17.602 -30.269,21.816 -27.103,24.982 -27.103,28.215 -26.589,28.729 U11.5@-25.613,28.729
GPIO31: J4/J2.17 U1.99 | length 50.7
  Top Signal w0.127: U1.99@-27.727,73.553 -27.077,74.202 -27.077,83.573 -30.891,87.386 -30.891,96.312 -29.822,97.38 -22.513,97.38 v1(-22.175,97.042)
  Bottom Signal w0.127: v1(-22.175,97.042) -21.81,96.677 -10.515,96.677 -9.763,95.924 -7.646,95.924 J4/J2.17@-6.351,94.629
GPIO32: J4/J2.18 R39.2 U1.64 | length 96.7
  Top Signal w0.127: U1.64@-23.484,59.269 -22.734,58.52 -22.734,56.58 v1(-21.134,54.98) -19.669,53.515 -19.193,53.515 -8.11,42.432 v1(-5.535,42.432) ; J4/J2.18@-6.351,97.169 -5.165,97.169 -4.121,96.125 -4.121,86.584 -1.855,84.317 v1(-1.855,42.432) v1@-1.911,42.432
  Bottom Signal w0.127: R39.2@-22.278,46.297 R39.2@-22.068,46.297 -22.479,46.708 -22.479,53.635 v1(-21.134,54.98) ; v1(-5.535,42.432) v1(-1.855,42.432) v1@-1.848,42.432
GPIO33: J8/J6.71 U1.53 | length 61.1
  Top Signal w0.127: U1.53@-27.373,55.38 -23.872,51.879 ; -23.863,51.879 -23.872,51.879 ; J8/J6.71@-8.891,15.889 -7.806,16.974 -5.731,16.974 -2.398,20.307 -2.398,27.579 -1.821,28.157 v1(-1.821,40.264) ; v1(-8.331,40.264) -9.581,40.264 -10.108,40.792 -10.108,42.039 -18.326,50.257 -18.758,50.257 -19.388,50.886 -19.388,50.893 -20.208,51.714 -23.707,51.714 -23.872,51.879
  Bottom Signal w0.127: v1(-8.331,40.264) v1(-1.821,40.264)
GPIO34: J1/J3.10 U1.94 | length 40.8
  Top Signal w0.127: J1/J3.10@-52.071,79.389 -50.979,80.481 -49.048,80.481 -48.134,79.567 -48.134,78.551 -46.712,77.128 -40.957,77.128 v1(-40.526,77.559) ; U1.94@-25.959,71.785 -25.249,72.495 -25.017,72.495 -24.309,73.204 v2(-24.309,80.278)
  Bottom Signal w0.127: v1(-40.526,77.559) -40.245,77.84 -39.439,77.84 -37.007,80.271 -24.315,80.271 v2(-24.309,80.278)
GPIO35: J8/J6.75 R44.1 U1.63 | length 49.5
  Top Signal w0.127: v1(-24.614,59.704) -24.614,59.692 U1.63@-23.837,58.916 -23.115,58.193 -23.115,56.341 -20.012,53.238 -19.308,53.238 -7.942,41.872 -6.739,41.872 -4.779,39.911 -4.779,26.223 -6.172,24.83 -7.672,24.83 J8/J6.75@-8.891,26.049
  GND w0.127: v1@-24.691,59.729 -24.665,59.704 v1(-24.614,59.704)
  Bottom Signal w0.127: R44.1@-24.828,60.782 -24.338,60.292 -24.338,59.98 v1(-24.614,59.704)
GPIO37: J8/J6.76 R45.1 U1.61 | length 46.2
  Top Signal w0.127: v1(-25.605,58.961) -25.297,58.961 U1.61@-24.545,58.209 -23.471,57.135 -23.471,56.305 -20.127,52.961 -19.439,52.961 -8.012,41.534 -6.793,41.534 -5.056,39.796 -5.056,28.183 -5.868,27.37 -7.672,27.37 J8/J6.76@-8.891,28.589
  Bottom Signal w0.127: R45.1@-26.555,58.957 -26.551,58.961 v1(-25.605,58.961)
GPIO40: U1.80 U13.3 | length 68
  Top Signal w0.127: U13.3@-27.019,17.602 -27.019,21.459 -25.299,23.179 -20.087,23.179 -17.273,25.993 v1(-17.273,40.959) ; U1.80@-21.009,66.836 v1(-17.73,70.114)
  Bottom Signal w0.127: v1(-17.73,70.114) -17.73,69.565 -17.361,69.195 -17.361,69.157 -12.922,64.719 -12.922,58.289 -17.273,53.938 -17.273,46.416 -17.269,46.411 -17.269,45.819 -17.273,45.814 v1(-17.273,40.959)
GPIO41: U1.82 U13.4 | length 68.8
  Top Signal w0.127: U13.4@-27.669,17.602 -27.669,21.647 -25.604,23.712 -20.146,23.712 -17.73,26.128 v1(-17.73,41.721) ; U1.82@-21.716,67.543 v1(-18.632,70.627)
  Bottom Signal w0.127: v1(-18.632,70.627) -18.632,70.075 -17.638,69.081 -17.638,69.043 -13.199,64.604 -13.199,58.404 -17.55,54.053 -17.55,46.301 -17.546,46.297 -17.546,45.933 -17.73,45.749 v1(-17.73,41.721)
GPIO44_FSITXCLK: J11.2 U1.85 | length 64.1
  Top Signal w0.127: U1.85@-22.777,68.603 -17.705,73.675 v2(-17.705,76.214) ; v2(-7.824,75.782) -7.824,75.579 -7.824,75.469 cw(c-7.951,75.469) -7.951,75.342 ccw(c-7.951,75.215) -8.078,75.215 ccw(c-7.951,75.215) -7.951,75.088 -7.824,75.088 -7.697,75.088 cw(c-7.697,74.961) -7.57,74.961 cw(c-7.697,74.961) -7.697,74.834 -7.824,74.834 -7.951,74.834 ccw(c-7.951,74.707) -8.078,74.707 ccw(c-7.951,74.707) -7.951,74.58 -7.824,74.58 -7.697,74.58 cw(c-7.697,74.453) -7.57,74.453 cw(c-7.697,74.453) -7.697,74.326 -7.824,74.326 -7.951,74.326 ccw(c-7.951,74.199) -8.078,74.199 ccw(c-7.951,74.199) -7.951,74.072 -7.824,74.072 -7.697,74.072 cw(c-7.697,73.945) -7.57,73.945 cw(c-7.697,73.945) -7.697,73.818 -7.824,73.818 -7.951,73.818 ccw(c-7.951,73.691) -8.078,73.691 ccw(c-7.951,73.691) -7.951,73.564 -7.824,73.564 -7.697,73.564 cw(c-7.697,73.437) -7.57,73.437 cw(c-7.697,73.437) -7.697,73.31 -7.824,73.31 -7.951,73.31 ccw(c-7.951,73.183) -8.078,73.183 ccw(c-7.951,73.183) -7.951,73.056 -7.824,73.056 -7.697,73.056 cw(c-7.697,72.929) -7.57,72.929 cw(c-7.697,72.929) -7.697,72.802 -7.824,72.802 -7.951,72.802 ccw(c-7.951,72.675) -8.078,72.675 ccw(c-7.951,72.675) -7.951,72.548 -7.824,72.548 -7.697,72.548 cw(c-7.697,72.421) -7.57,72.421 cw(c-7.697,72.421) -7.697,72.294 -7.824,72.294 -7.951,72.294 ccw(c-7.951,72.167) -8.078,72.167 ccw(c-7.951,72.167) -7.951,72.04 -7.824,72.04 -7.697,72.04 cw(c-7.697,71.913) -7.57,71.913 cw(c-7.697,71.913) -7.697,71.786 -7.824,71.786 -7.951,71.786 ccw(c-7.951,71.659) -8.078,71.659 ccw(c-7.951,71.659) -7.951,71.532 -7.824,71.532 -7.697,71.532 cw(c-7.697,71.405) -7.57,71.405 cw(c-7.697,71.405) -7.697,71.278 -7.824,71.278 -7.951,71.278 ccw(c-7.951,71.151) -8.078,71.151 ccw(c-7.951,71.151) -7.951,71.024 -7.824,71.024 -7.697,71.024 cw(c-7.697,70.897) -7.57,70.897 cw(c-7.697,70.897) -7.697,70.77 -7.824,70.77 -7.951,70.77 ccw(c-7.951,70.643) -8.078,70.643 ccw(c-7.951,70.643) -7.951,70.516 -7.824,70.516 -7.697,70.516 cw(c-7.697,70.389) -7.57,70.389 cw(c-7.697,70.389) -7.697,70.262 -7.824,70.262 -7.951,70.262 ccw(c-7.951,70.135) -8.078,70.135 ccw(c-7.951,70.135) -7.951,70.008 -7.824,70.008 -7.697,70.008 cw(c-7.697,69.881) -7.57,69.881 cw(c-7.697,69.881) -7.697,69.754 -7.824,69.754 -7.951,69.754 ccw(c-7.951,69.627) -8.078,69.627 ccw(c-7.951,69.627) -7.951,69.5 -7.824,69.5 -7.697,69.5 cw(c-7.697,69.373) -7.57,69.373 cw(c-7.697,69.373) -7.697,69.246 -7.824,69.246 -7.951,69.246 ccw(c-7.951,69.119) -8.078,69.119 ccw(c-7.951,69.119) -7.951,68.992 -7.824,68.992 -7.697,68.992 cw(c-7.697,68.865) -7.57,68.865 cw(c-7.697,68.865) -7.697,68.738 -7.824,68.738 -7.951,68.738 ccw(c-7.951,68.611) -8.078,68.611 ccw(c-7.951,68.611) -7.951,68.484 -7.824,68.484 -7.697,68.484 cw(c-7.697,68.357) -7.57,68.357 cw(c-7.697,68.357) -7.697,68.23 -7.824,68.23 -7.951,68.23 ccw(c-7.951,68.103) -8.078,68.103 ccw(c-7.951,68.103) -7.951,67.976 -7.824,67.976 -7.697,67.976 cw(c-7.697,67.849) -7.57,67.849 cw(c-7.697,67.849) -7.697,67.722 -7.824,67.722 -7.951,67.722 ccw(c-7.951,67.595) -8.078,67.595 ccw(c-7.951,67.595) -7.951,67.468 -7.824,67.468 -7.697,67.468 cw(c-7.697,67.341) -7.57,67.341 cw(c-7.697,67.341) -7.697,67.214 -7.824,67.214 -7.951,67.214 ccw(c-7.951,67.087) -8.078,67.087 ccw(c-7.951,67.087) -7.951,66.96 -7.824,66.96 -7.697,66.96 cw(c-7.697,66.833) -7.57,66.833 cw(c-7.697,66.833) -7.697,66.706 -7.824,66.706 -7.951,66.706 ccw(c-7.951,66.579) -8.078,66.579 ccw(c-7.951,66.579) -7.951,66.452 -7.824,66.452 -7.697,66.452 cw(c-7.697,66.325) -7.57,66.325 cw(c-7.697,66.325) -7.697,66.198 ccw(c-7.697,66.071) -7.824,66.071 -7.824,65.944 -7.824,65.817 -7.824,65.521 -7.693,65.389 -7.444,65.389 -7.138,65.114 -7.138,64.708 ccw(c-7.011,64.708) -7.011,64.581 -7.015,64.581 cw(c-7.015,64.454) -6.888,64.454 cw(c-7.015,64.454) -7.015,64.327 -7.138,64.327 -7.261,64.327 ccw(c-7.261,64.2) -7.388,64.2 ccw(c-7.261,64.2) -7.261,64.073 -7.138,64.073 -7.015,64.073 cw(c-7.015,63.946) -6.888,63.946 cw(c-7.015,63.946) -7.015,63.819 -7.138,63.819 -7.261,63.819 ccw(c-7.261,63.692) -7.388,63.692 ccw(c-7.261,63.692) -7.261,63.565 -7.138,63.565 -7.015,63.565 cw(c-7.015,63.438) -6.888,63.438 cw(c-7.015,63.438) -7.015,63.311 -7.138,63.311 -7.261,63.311 ccw(c-7.261,63.184) -7.388,63.184 ccw(c-7.261,63.184) -7.261,63.057 -7.138,63.057 -7.015,63.057 cw(c-7.015,62.93) -6.888,62.93 cw(c-7.015,62.93) -7.015,62.803 -7.138,62.803 -7.261,62.803 ccw(c-7.261,62.676) -7.388,62.676 ccw(c-7.261,62.676) -7.261,62.549 -7.138,62.549 -7.015,62.549 cw(c-7.015,62.422) -6.888,62.422 cw(c-7.015,62.422) -7.015,62.295 -7.138,62.295 -7.261,62.295 ccw(c-7.261,62.168) -7.388,62.168 ccw(c-7.261,62.168) -7.261,62.041 -7.138,62.041 -7.015,62.041 cw(c-7.015,61.914) -6.888,61.914 cw(c-7.015,61.914) -7.015,61.787 -7.138,61.787 -7.261,61.787 ccw(c-7.261,61.66) -7.388,61.66 ccw(c-7.261,61.66) -7.261,61.533 -7.138,61.533 -7.015,61.533 cw(c-7.015,61.406) -6.888,61.406 cw(c-7.015,61.406) -7.015,61.279 -7.138,61.279 -7.261,61.279 ccw(c-7.261,61.152) -7.388,61.152 ccw(c-7.261,61.152) -7.261,61.025 -7.138,61.025 -7.015,61.025 cw(c-7.015,60.898) -6.888,60.898 cw(c-7.015,60.898) -7.015,60.771 -7.138,60.771 -7.261,60.771 ccw(c-7.261,60.644) -7.388,60.644 ccw(c-7.261,60.644) -7.261,60.517 -7.138,60.517 -7.015,60.517 cw(c-7.015,60.39) -6.888,60.39 cw(c-7.015,60.39) -7.015,60.263 -7.138,60.263 -7.261,60.263 ccw(c-7.261,60.136) -7.388,60.136 ccw(c-7.261,60.136) -7.261,60.009 -7.138,60.009 -7.015,60.009 cw(c-7.015,59.882) -6.888,59.882 cw(c-7.015,59.882) -7.015,59.755 -7.138,59.755 -7.261,59.755 ccw(c-7.261,59.628) -7.388,59.628 ccw(c-7.261,59.628) -7.261,59.501 -7.138,59.501 -7.015,59.501 cw(c-7.015,59.374) -6.888,59.374 cw(c-7.015,59.374) -7.015,59.247 -7.138,59.247 -7.261,59.247 ccw(c-7.261,59.12) -7.388,59.12 ccw(c-7.261,59.12) -7.261,58.993 -7.138,58.993 -7.015,58.993 cw(c-7.015,58.866) -6.888,58.866 cw(c-7.015,58.866) -7.015,58.739 -7.138,58.739 -7.261,58.739 ccw(c-7.261,58.612) -7.388,58.612 ccw(c-7.261,58.612) -7.261,58.485 -7.138,58.485 -7.015,58.485 cw(c-7.015,58.358) -6.888,58.358 cw(c-7.015,58.358) -7.015,58.231 -7.138,58.231 -7.265,58.231 ccw(c-7.265,58.104) -7.392,58.104 ccw(c-7.265,58.104) -7.265,57.977 cw(c-7.265,57.85) -7.138,57.85 -7.138,57.723 -7.138,57.469 -7.138,57.342 -7.138,57.316 J11.2@-6.351,56.529
  Bottom Signal w0.127: v2(-17.705,76.214) -8.256,76.214 v2(-7.824,75.782)
GPIO47: J4/J2.12 U1.6 | length 36
  Top Signal w0.127: U1.6@-32.111,72.139 -32.761,72.789 -32.761,73.086 -31.82,74.027 -31.82,81.313 v1(-31.827,81.319)
  Bottom Signal w0.127: v1(-31.827,81.319) -10.339,81.319 -9.831,80.811 -7.469,80.811 J4/J2.12@-6.351,81.929
GPIO48: J4/J2.11 U1.7 | length 36.3
  Top Signal w0.127: U1.7@-32.464,71.785 -33.101,72.422 -33.101,73.226 -32.259,74.068 v1(-32.259,80.71)
  Bottom Signal w0.127: v1(-32.259,80.71) -31.522,80.71 -31.19,81.042 -10.722,81.042 -10.161,80.481 -7.443,80.481 J4/J2.11@-6.351,79.389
